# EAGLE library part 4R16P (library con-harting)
CONNECTOR
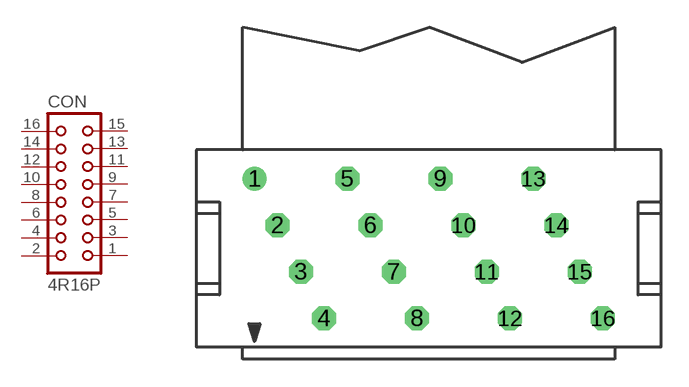
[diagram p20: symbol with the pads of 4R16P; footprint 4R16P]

Designator prefix CON

## 4R16P (OC_FARNELL: unknown; OC_NEWARK: unknown)  [4R16P]
1  1  pas
2  2  pas
3  3  pas
4  4  pas
5  5  pas
6  6  pas
7  7  pas
8  8  pas
9  9  pas
10  10  pas
11  11  pas
12  12  pas
13  13  pas
14  14  pas
15  15  pas
16  16  pas

## Footprint 4R16P (pad centres in mm)
CONNECTOR
drill 0.813 round: 1 -9.525,3.81
drill 0.813 octagon: 2 -8.255,1.27; 3 -6.985,-1.27; 4 -5.715,-3.81; 5 -4.445,3.81; 6 -3.175,1.27; 7 -1.905,-1.27; 8 -0.635,-3.81; 9 0.635,3.81; 10 1.905,1.27; 11 3.175,-1.27; 12 4.445,-3.81; 13 5.715,3.81; 14 6.985,1.27; 15 8.255,-1.27; 16 9.525,-3.81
